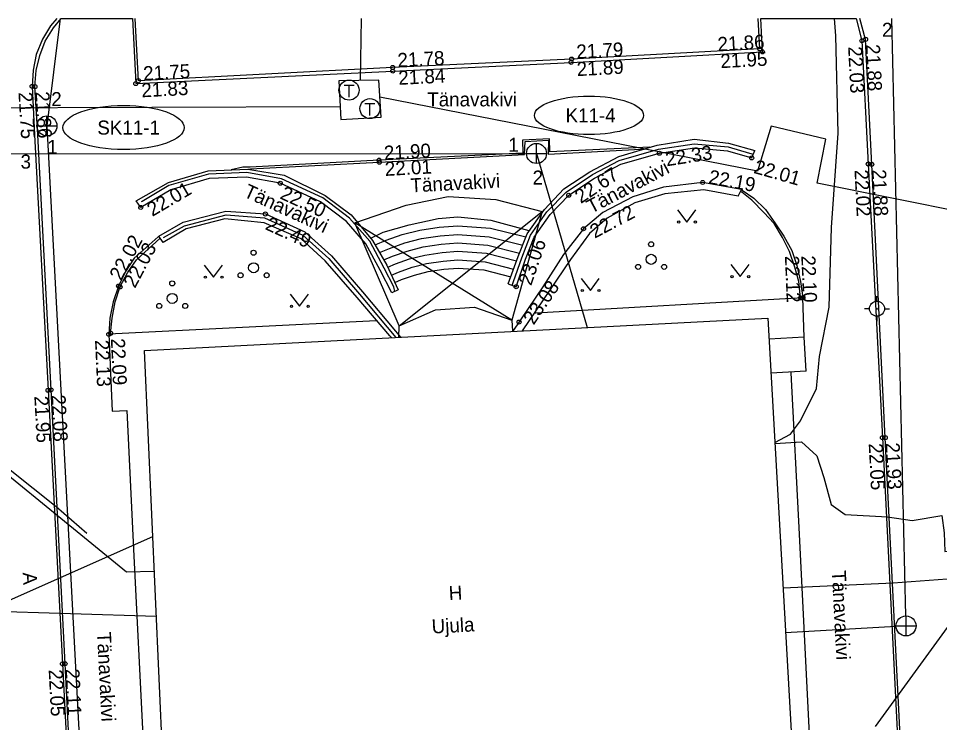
# Model space of a CAD drawing. Extents: x 714038 to 714279, y 6589845 to 6590041.
# Drawn here: x 714116.25 to 714162.18, y 6590005.87 to 6590040.97 of the extents above; entities that cross this region are included whole.
import ezdxf

# ---------------------------------------------------------------- set-up
doc = ezdxf.new("R2010")
doc.units = 0
for name, color, linetype in [('ALUSVORK', 7, 'Continuous'), ('HALJASTUS', 7, 'Continuous'), ('HOONE', 7, 'Continuous'), ('HOONEDET', 7, 'Continuous'), ('KAEVU_NR', 7, 'Continuous'), ('KKAEV', 7, 'Continuous'), ('KORGUS', 7, 'Continuous'), ('KTRASS', 7, 'Continuous'), ('LIIKLUS', 7, 'Continuous'), ('PUU', 7, 'Continuous'), ('RAJATIS', 7, 'Continuous'), ('SITRASS', 7, 'Continuous'), ('SKKAEV', 7, 'Continuous'), ('SKTRASS', 7, 'Continuous'), ('TEE', 7, 'Continuous'), ('TKAEV', 7, 'Continuous'), ('TORU NR', 7, 'Continuous'), ('TTRASS', 7, 'Continuous'), ('VTRASS', 7, 'Continuous')]:
    doc.layers.add(name, color=color, linetype=linetype)

msp = doc.modelspace()

# ---------------------------------------------------------------- linework, layer by layer
at = {"layer": 'ALUSVORK'}
for p, q in [((714159.055, 6590026.875), (714159.055, 6590027.125)), ((714158.68, 6590026.5), (714158.43, 6590026.5)), ((714159.43, 6590026.5), (714159.68, 6590026.5)), ((714159.055, 6590026.125), (714159.055, 6590025.875))]:
    msp.add_line(p, q, dxfattribs=at)
for radius in [0.375, 0.022]:
    msp.add_circle((714159.055, 6590026.5), radius, dxfattribs=at)
at = {"layer": 'HALJASTUS'}
for p, q in [((714149.109, 6590031.427), (714149.572, 6590030.82)), ((714149.572, 6590030.82), (714150.018, 6590031.427)), ((714151.77, 6590028.706), (714152.233, 6590028.099)), ((714152.233, 6590028.099), (714152.679, 6590028.706)), ((714125.51, 6590028.676), (714125.973, 6590028.069)), ((714125.973, 6590028.069), (714126.419, 6590028.676)), ((714144.3, 6590028.011), (714144.764, 6590027.404)), ((714144.764, 6590027.404), (714145.209, 6590028.011)), ((714129.804, 6590027.225), (714130.267, 6590026.618)), ((714130.267, 6590026.618), (714130.713, 6590027.225))]:
    msp.add_line(p, q, dxfattribs=at)
for centre in [(714149.171, 6590030.82), (714150, 6590030.82), (714125.572, 6590028.069), (714126.401, 6590028.069), (714151.832, 6590028.099), (714152.661, 6590028.099), (714144.363, 6590027.404), (714145.192, 6590027.404), (714129.866, 6590026.618), (714130.695, 6590026.618)]:
    msp.add_circle(centre, 0.055, dxfattribs=at)
at = {"layer": 'HOONE'}
for points in [[(714135.226, 6590025.643), (714133.02, 6590030.786), (714135.575, 6590031.653), (714137.67, 6590032.083), (714140.058, 6590031.943), (714142.37, 6590031.339), (714140.847, 6590025.921)], [(714123.806, 6589995.811), (714122.528, 6590024.418), (714153.616, 6590026.033), (714155.226, 6589997.511)]]:
    msp.add_lwpolyline(points, dxfattribs=at)
at = {"layer": 'HOONEDET'}
for p, q in [((714135.226, 6590025.643), (714137.049, 6590026.438)), ((714137.049, 6590026.438), (714138.994, 6590026.569)), ((714138.994, 6590026.569), (714140.847, 6590025.921)), ((714135.218, 6590025.061), (714135.226, 6590025.643)), ((714140.847, 6590025.921), (714140.89, 6590025.372))]:
    msp.add_line(p, q, dxfattribs=at)
for points in [[(714135.226, 6590025.643), (714142.37, 6590031.339)], [(714140.847, 6590025.921), (714133.02, 6590030.786)], [(714155.433, 6590025.074), (714155.354, 6590027.044), (714142.04, 6590026.282), (714141.962, 6590026.278)], [(714134.084, 6590025.899), (714120.754, 6590025.223), (714120.927, 6590021.387), (714121.652, 6590021.434), (714122.002, 6590014.168), (714122.456, 6590005.222), (714121.784, 6590005.188), (714122.031, 6590000.695), (714122.737, 6590000.728), (714122.997, 6589994.9)], [(714156.127, 6589996.644), (714155.189, 6590015.256), (714154.783, 6590023.3), (714154.78, 6590023.348)]]:
    msp.add_lwpolyline(points, dxfattribs=at)
at = {"layer": 'KAEVU_NR'}
for centre, major_axis, ratio in [((714144.698, 6590036.134), (2.717, 0), 0.353371), ((714121.489, 6590035.525), (-3.02, 0), 0.364056)]:
    msp.add_ellipse(centre, major_axis=major_axis, ratio=ratio, dxfattribs=at)
at = {"layer": 'KKAEV'}
for p, q in [((714142.079, 6590033.735), (714142.079, 6590034.735)), ((714141.579, 6590034.235), (714142.579, 6590034.235))]:
    msp.add_line(p, q, dxfattribs=at)
msp.add_circle((714142.079, 6590034.235), 0.5, dxfattribs=at)
at = {"layer": 'KORGUS'}
for centre in [(714158.303, 6590039.85), (714158.488, 6590039.922), (714153.206, 6590039.447), (714153.346, 6590039.301), (714143.807, 6590038.773), (714143.828, 6590038.94), (714134.905, 6590038.523), (714134.914, 6590038.34), (714122.227, 6590037.861), (714116.932, 6590037.581), (714117.073, 6590037.566), (714122.099, 6590037.718), (714148.204, 6590034.245), (714134.233, 6590033.901), (714134.24, 6590033.799), (714152.809, 6590034.015), (714158.62, 6590033.709), (714158.792, 6590033.69), (714129.303, 6590032.752), (714150.364, 6590032.791), (714143.685, 6590032.152), (714122.346, 6590031.544), (714128.561, 6590031.219), (714144.423, 6590030.482), (714121.241, 6590027.63), (714121.317, 6590027.583), (714141.065, 6590027.594), (714155.249, 6590027.039), (714155.365, 6590027.052), (714141.21, 6590025.833), (714120.754, 6590025.223), (714120.845, 6590025.268), (714117.725, 6590022.434), (714117.88, 6590022.454), (714159.328, 6590020.072), (714159.469, 6590020.069), (714118.442, 6590008.801), (714118.575, 6590008.805)]:
    msp.add_circle(centre, 0.1, dxfattribs=at)
at = {"layer": 'KTRASS'}
for points in [[(714115.68, 6590034.214), (714142.079, 6590034.235)], [(714142.079, 6590034.235), (714144.604, 6590025.565)], [(714114.583, 6590011.444), (714122.942, 6590015.15)], [(714114.552, 6590011.45), (714123.119, 6590011.176)]]:
    msp.add_lwpolyline(points, dxfattribs=at)
at = {"layer": 'LIIKLUS'}
for points in [[(714140.867, 6590027.663), (714140.94, 6590027.851), (714141.346, 6590029.032), (714141.78, 6590030.163), (714142.598, 6590031.322), (714143.555, 6590032.308), (714144.876, 6590033.184), (714146.201, 6590033.886), (714148.161, 6590034.442), (714149.946, 6590034.721), (714151.641, 6590034.558), (714152.696, 6590034.257), (714152.89, 6590034.197)], [(714135.022, 6590027.359), (714134.964, 6590027.582), (714134.492, 6590028.522), (714133.762, 6590029.857), (714132.758, 6590031.019), (714131.427, 6590032.024), (714129.372, 6590032.97), (714127.639, 6590033.286), (714125.728, 6590033.208), (714123.751, 6590032.632), (714122.417, 6590031.849), (714122.364, 6590031.817)], [(714123.48, 6590030.045), (714124.529, 6590030.636), (714126.607, 6590031.172), (714128.513, 6590031.032), (714130.421, 6590030.162), (714131.725, 6590028.997), (714133.258, 6590027.225), (714135.059, 6590025.069)]]:
    msp.add_lwpolyline(points, dxfattribs=at)
at = {"layer": 'PUU'}
for centre, radius in [((714147.794, 6590029.709), 0.125), ((714127.975, 6590029.289), 0.125), ((714147.794, 6590028.959), 0.25), ((714127.975, 6590028.539), 0.25), ((714147.144, 6590028.584), 0.125), ((714148.444, 6590028.584), 0.125), ((714127.325, 6590028.164), 0.125), ((714128.625, 6590028.164), 0.125), ((714123.918, 6590027.761), 0.125), ((714123.918, 6590027.011), 0.25), ((714123.268, 6590026.636), 0.125), ((714124.568, 6590026.636), 0.125)]:
    msp.add_circle(centre, radius, dxfattribs=at)
at = {"layer": 'RAJATIS'}
for points in [[(714140.669, 6590027.731), (714141.163, 6590029.094), (714141.621, 6590030.238), (714142.473, 6590031.441), (714143.444, 6590032.47), (714144.745, 6590033.323), (714146.189, 6590034.077), (714148.089, 6590034.653), (714149.934, 6590034.949), (714151.645, 6590034.754), (714152.971, 6590034.38)], [(714122.127, 6590031.875), (714123.731, 6590032.789), (714125.701, 6590033.373), (714127.689, 6590033.456), (714129.49, 6590033.162), (714131.541, 6590032.143), (714132.832, 6590031.178), (714133.908, 6590029.902), (714134.616, 6590028.673), (714135.185, 6590027.434)], [(714152.129, 6590032.115), (714150.424, 6590032.417), (714148.48, 6590032.232), (714146.989, 6590031.775), (714145.606, 6590031.016), (714144.718, 6590030.241), (714143.779, 6590028.953), (714141.364, 6590025.397)], [(714134.761, 6590025.155), (714133.131, 6590027.059), (714131.539, 6590028.891), (714130.341, 6590029.989), (714128.494, 6590030.777), (714126.533, 6590030.983), (714124.613, 6590030.487), (714123.467, 6590029.802)]]:
    msp.add_lwpolyline(points, dxfattribs=at)
at = {"layer": 'SITRASS'}
for points in [[(714153.966, 6590019.835), (714154.738, 6590020.25), (714155.241, 6590020.905), (714156.044, 6590022.523), (714156.187, 6590024.113), (714156.669, 6590026.569), (714156.78, 6590030.55), (714157.113, 6590035.251), (714157.004, 6590040.103), (714156.942, 6590040.965)], [(714119.667, 6590015.291), (714118.134, 6590016.633), (714114.596, 6590019.438), (714107.457, 6590025.877), (714104.409, 6590029.065), (714100.251, 6590033.606)], [(714153.969, 6590019.777), (714155.294, 6590019.865), (714156.05, 6590019.166), (714156.398, 6590018.084), (714156.778, 6590016.734), (714157.468, 6590016.238), (714159.581, 6590016.127), (714160.804, 6590015.95), (714162.282, 6590016.195), (714162.403, 6590015.338), (714162.44, 6590014.401), (714164.294, 6590014.521), (714168.017, 6590014.987), (714169.99, 6590015.378), (714173.537, 6590015.781), (714175.12, 6590015.912)], [(714154.374, 6590012.596), (714159.865, 6590012.844), (714163.01, 6590013.069), (714166.345, 6590013.02), (714169.914, 6590013.444), (714174.135, 6590014.18), (714175.181, 6590014.334)]]:
    msp.add_lwpolyline(points, dxfattribs=at)
at = {"layer": 'SKKAEV'}
for p, q in [((714117.671, 6590035.109), (714117.671, 6590036.109)), ((714117.171, 6590035.609), (714118.171, 6590035.609)), ((714160.503, 6590010.19), (714160.503, 6590011.19)), ((714160.003, 6590010.69), (714161.003, 6590010.69))]:
    msp.add_line(p, q, dxfattribs=at)
for centre in [(714117.671, 6590035.609), (714160.503, 6590010.69)]:
    msp.add_circle(centre, 0.5, dxfattribs=at)
at = {"layer": 'SKTRASS'}
for points in [[(714118.331, 6590040.965), (714117.671, 6590035.609)], [(714160.491, 6590011.19), (714159.788, 6590040.965)], [(714117.671, 6590035.609), (714120.007, 6589991.394)], [(714158.983, 6590005.685), (714168.6, 6590018.903)], [(714160.004, 6590010.662), (714154.501, 6590010.351)]]:
    msp.add_lwpolyline(points, dxfattribs=at)
at = {"layer": 'TEE'}
for p, q in [((714117.994, 6590040.489), (714118.385, 6590040.965)), ((714118.385, 6590040.965), (714121.944, 6590040.965)), ((714121.944, 6590040.965), (714122.099, 6590037.718)), ((714153.346, 6590039.301), (714153.258, 6590040.965)), ((714153.258, 6590040.965), (714158.012, 6590040.965)), ((714158.012, 6590040.965), (714158.303, 6590039.85)), ((714117.588, 6590039.837), (714117.994, 6590040.489)), ((714117.312, 6590039.111), (714117.588, 6590039.837)), ((714158.303, 6590039.85), (714158.62, 6590033.709)), ((714143.807, 6590038.773), (714153.346, 6590039.301)), ((714117.125, 6590038.378), (714117.312, 6590039.111)), ((714117.073, 6590037.566), (714117.125, 6590038.378)), ((714134.914, 6590038.34), (714143.807, 6590038.773)), ((714122.099, 6590037.718), (714134.914, 6590038.34)), ((714117.215, 6590035.159), (714117.073, 6590037.566)), ((714117.88, 6590022.454), (714117.215, 6590035.159)), ((714158.62, 6590033.709), (714159.328, 6590020.072)), ((714118.575, 6590008.805), (714117.88, 6590022.454)), ((714159.328, 6590020.072), (714160.175, 6590003.23)), ((714119.214, 6589995.92), (714118.575, 6590008.805))]:
    msp.add_line(p, q, dxfattribs=at)
for points in [[(714118.17, 6590040.965), (714117.844, 6590040.591), (714117.445, 6590039.93), (714117.134, 6590039.169), (714116.988, 6590038.386), (714116.932, 6590037.581), (714117.045, 6590035.166), (714117.725, 6590022.434), (714118.442, 6590008.801), (714119.224, 6589993.603), (714119.563, 6589992.698), (714120.198, 6589991.881), (714121.032, 6589991.362), (714122.012, 6589991.089), (714123.012, 6589991.123), (714130.695, 6589991.494), (714142.938, 6589992.169), (714155.474, 6589992.859)], [(714153.118, 6590040.965), (714153.206, 6590039.447), (714143.828, 6590038.94), (714134.905, 6590038.523), (714122.227, 6590037.861), (714122.077, 6590040.965)], [(714155.474, 6589992.859), (714155.637, 6589989.831), (714155.711, 6589989.359), (714155.917, 6589988.897), (714156.482, 6589988.156), (714156.88, 6589987.871), (714157.331, 6589987.632), (714157.808, 6589987.528), (714158.276, 6589987.496), (714158.764, 6589987.53), (714159.668, 6589987.878), (714160.04, 6589988.133), (714160.305, 6589988.353), (714160.603, 6589988.76), (714160.81, 6589989.189), (714160.975, 6589990.123), (714160.841, 6589993.165), (714160.313, 6590003.239), (714159.469, 6590020.069), (714158.792, 6590033.69), (714158.488, 6590039.922), (714158.196, 6590040.965)], [(714147.733, 6590034.545), (714142.751, 6590034.311), (714142.73, 6590034.965), (714141.382, 6590034.895), (714141.401, 6590034.256), (714134.233, 6590033.901), (714127.804, 6590033.559), (714127.445, 6590033.555), (714126.86, 6590033.421)], [(714127.689, 6590033.456), (714127.825, 6590033.468), (714134.24, 6590033.799), (714141.476, 6590034.185), (714141.507, 6590034.824), (714142.675, 6590034.896), (714142.657, 6590034.202), (714147.28, 6590034.455), (714147.451, 6590034.457)], [(714140.669, 6590027.731), (714141.065, 6590027.594), (714141.536, 6590028.963), (714141.959, 6590030.067), (714142.754, 6590031.193), (714143.685, 6590032.152), (714144.979, 6590033.01), (714146.277, 6590033.698), (714148.204, 6590034.245), (714149.952, 6590034.518), (714151.603, 6590034.359), (714152.809, 6590034.015), (714152.971, 6590034.38)], [(714135.185, 6590027.434), (714134.86, 6590027.283), (714134.291, 6590028.416), (714133.574, 6590029.727), (714132.602, 6590030.852), (714131.31, 6590031.828), (714129.303, 6590032.752), (714127.623, 6590033.058), (714125.765, 6590032.982), (714123.842, 6590032.422), (714122.346, 6590031.544), (714122.127, 6590031.875)], [(714152.129, 6590032.115), (714152.299, 6590032.432), (714150.364, 6590032.791), (714148.414, 6590032.563), (714146.88, 6590032.077), (714145.387, 6590031.29), (714144.423, 6590030.482), (714143.432, 6590029.201), (714142.399, 6590027.581), (714140.897, 6590025.372)], [(714152.299, 6590032.432), (714152.332, 6590032.402), (714152.914, 6590032.003), (714153.492, 6590031.438), (714153.965, 6590030.779), (714154.405, 6590030.106), (714154.813, 6590029.399), (714155.067, 6590028.656), (714155.25, 6590027.861), (714155.354, 6590027.044)], [(714155.354, 6590027.044), (714155.249, 6590027.039), (714155.158, 6590027.849), (714154.959, 6590028.564), (714154.689, 6590029.348), (714154.345, 6590030.048), (714153.93, 6590030.745), (714153.412, 6590031.3), (714152.815, 6590031.91), (714152.314, 6590032.304), (714152.248, 6590032.337)], [(714123.467, 6590029.802), (714123.255, 6590030.109), (714124.456, 6590030.814), (714126.59, 6590031.364), (714128.561, 6590031.219), (714130.526, 6590030.323), (714131.861, 6590029.131), (714133.403, 6590027.348), (714135.047, 6590025.381), (714135.297, 6590025.082)], [(714133.811, 6590030.017), (714134.43, 6590030.316), (714135.732, 6590030.685), (714135.732, 6590030.685), (714137.174, 6590030.995), (714138.16, 6590031.073), (714139.807, 6590030.91), (714141.7, 6590030.395)], [(714134.037, 6590029.679), (714134.587, 6590029.91), (714135.384, 6590030.193), (714136.263, 6590030.415), (714137.224, 6590030.563), (714138.161, 6590030.637), (714139.785, 6590030.517), (714141.555, 6590030.073)], [(714123.255, 6590030.109), (714123.212, 6590030.088), (714122.024, 6590029.016), (714121.579, 6590028.352), (714121.241, 6590027.63), (714120.975, 6590026.841), (714120.813, 6590026.034), (714120.754, 6590025.223)], [(714134.255, 6590029.3), (714134.744, 6590029.506), (714135.51, 6590029.778), (714136.349, 6590029.99), (714137.274, 6590030.132), (714138.162, 6590030.202), (714139.716, 6590030.087), (714141.392, 6590029.667)], [(714120.845, 6590025.268), (714120.922, 6590026.035), (714121.068, 6590026.846), (714121.326, 6590027.614), (714121.681, 6590028.281), (714122.133, 6590028.931), (714123.32, 6590030.016)], [(714134.467, 6590028.932), (714134.896, 6590029.113), (714135.632, 6590029.374), (714136.433, 6590029.576), (714137.323, 6590029.713), (714138.163, 6590029.779), (714139.648, 6590029.669), (714141.234, 6590029.272)], [(714134.663, 6590028.57), (714135.044, 6590028.731), (714135.751, 6590028.982), (714136.514, 6590029.174), (714137.37, 6590029.306), (714138.164, 6590029.368), (714139.583, 6590029.263), (714141.088, 6590028.887)], [(714134.845, 6590028.174), (714135.202, 6590028.324), (714135.878, 6590028.564), (714136.601, 6590028.746), (714137.42, 6590028.872), (714138.165, 6590028.931), (714139.513, 6590028.831), (714140.938, 6590028.474)], [(714135.014, 6590027.807), (714135.348, 6590027.947), (714135.995, 6590028.177), (714136.681, 6590028.35), (714137.467, 6590028.471), (714138.166, 6590028.526), (714139.449, 6590028.431), (714140.803, 6590028.092)], [(714134.761, 6590025.155), (714134.844, 6590025.058)], [(714155.52, 6590023.39), (714155.433, 6590025.074), (714153.676, 6590024.975)], [(714155.52, 6590023.39), (714153.771, 6590023.291)]]:
    msp.add_lwpolyline(points, dxfattribs=at)
at = {"layer": 'TKAEV'}
for p, q in [((714132.482, 6590037.642), (714132.982, 6590037.642)), ((714132.732, 6590037.042), (714132.732, 6590037.642)), ((714133.525, 6590036.721), (714134.025, 6590036.721)), ((714133.775, 6590036.121), (714133.775, 6590036.721))]:
    msp.add_line(p, q, dxfattribs=at)
for centre in [(714132.732, 6590037.392), (714133.775, 6590036.471)]:
    msp.add_circle(centre, 0.5, dxfattribs=at)
at = {"layer": 'TTRASS'}
for points in [[(714133.31, 6590037.87), (714133.351, 6590040.965)], [(714132.293, 6590036.559), (714113.5, 6590036.5), (714113.45, 6590038.15), (714110.55, 6590038.15), (714110.573, 6590036.38), (714092.848, 6590036.126)], [(714171.653, 6590030.531), (714167.33, 6590030.49), (714156.069, 6590032.753), (714156.51, 6590034.95), (714153.78, 6590035.59), (714153.09, 6590033.35), (714134.271, 6590037.038)]]:
    msp.add_lwpolyline(points, dxfattribs=at)
msp.add_lwpolyline([(714132.328, 6590035.93), (714134.328, 6590036.044), (714134.222, 6590037.893), (714132.223, 6590037.858)], close=True, dxfattribs=at)
at = {"layer": 'VTRASS'}
msp.add_lwpolyline([(714110.18, 6590040.965), (714110.16, 6590022.75), (714121.63, 6590013.38), (714123.019, 6590013.414)], dxfattribs=at)

# ---------------------------------------------------------------- texts
at = {"layer": 'HOONE'}
for s, p in [('H', (714137.721, 6590011.971)), ('Ujula', (714136.87, 6590010.309))]:
    msp.add_text(s, height=0.7, rotation=2.9733, dxfattribs=at).set_placement(p)
at = {"layer": 'KAEVU_NR'}
for s, p in [('K11-4', (714143.528, 6590035.784)), ('SK11-1', (714120.182, 6590035.175))]:
    msp.add_text(s, height=0.7, dxfattribs=at).set_placement(p)
at = {"layer": 'KORGUS'}
for s, rotation, p in [(' 21.79', 3.0946, (714143.828, 6590038.94)), (' 21.86', 3.1682, (714150.865, 6590039.317)), (' 21.78', 2.7875, (714134.905, 6590038.523)), (' 21.95', 3.1682, (714151.008, 6590038.471)), (' 22.03', 272.7927, (714157.604, 6590039.816)), (' 21.88', 272.7927, (714158.488, 6590039.922)), (' 21.89', 3.0946, (714143.845, 6590038.074)), (' 21.75', 2.9891, (714122.227, 6590037.861)), (' 21.84', 2.7875, (714134.948, 6590037.641)), (' 21.83', 2.9891, (714122.136, 6590037.019)), (' 21.75', 273.3762, (714116.233, 6590037.54)), (' 21.86', 273.3762, (714117.073, 6590037.566)), (' 21.90', 3.0535, (714134.233, 6590033.901)), (' 22.33', 8.8767, (714148.312, 6590033.553)), (' 22.01', 3.0535, (714134.277, 6590033.1)), (' 22.01', 344.0797, (714152.617, 6590033.342)), (' 22.67', 33.5468, (714144.072, 6590031.569)), (' 22.19', 349.4894, (714150.364, 6590032.791)), (' 22.02', 272.8454, (714157.921, 6590033.674)), (' 21.88', 272.8454, (714158.792, 6590033.69)), (' 22.01', 30.4086, (714122.7, 6590030.94)), (' 22.50', 335.2792, (714129.01, 6590032.116)), (' 22.72', 27.7949, (714144.749, 6590029.863)), (' 22.49', 335.488, (714128.271, 6590030.582)), (' 22.02', 61.9766, (714121.241, 6590027.63)), (' 22.03', 61.9766, (714121.935, 6590027.254)), (' 23.06', 71.0144, (714141.727, 6590027.366)), (' 22.12', 272.2964, (714154.454, 6590029.389)), (' 22.10', 272.2964, (714155.271, 6590029.395)), (' 23.08', 55.7762, (714141.789, 6590025.439)), (' 22.13', 272.5822, (714120.055, 6590025.191)), (' 22.09', 272.5822, (714120.845, 6590025.268)), (' 21.95', 273.0106, (714117.026, 6590022.397)), (' 22.08', 273.0106, (714117.88, 6590022.454)), (' 22.05', 272.8709, (714158.629, 6590020.037)), (' 21.93', 272.8709, (714159.469, 6590020.069)), (' 22.11', 272.8391, (714118.575, 6590008.805)), (' 22.05', 272.8391, (714117.743, 6590008.766))]:
    msp.add_text(s, height=0.7, rotation=rotation, dxfattribs=at).set_placement(p)
at = {"layer": 'TEE'}
msp.add_text('Tänavakivi', height=0.7, dxfattribs=at).set_placement((714136.633, 6590036.581))
for s, rotation, p in [('Tänavakivi', 27.7949, (714144.814, 6590031.217)), ('Tänavakivi', 3.0535, (714135.814, 6590032.292)), ('Tänavakivi', 335.488, (714127.426, 6590032.105)), ('A', 272.8364, (714116.463, 6590013.348)), ('Tänavakivi', 272.8851, (714156.803, 6590013.44)), ('Tänavakivi', 273.0106, (714120.161, 6590010.372))]:
    msp.add_text(s, height=0.7, rotation=rotation, dxfattribs=at).set_placement(p)
at = {"layer": 'TORU NR'}
for s, p in [('2', (714159.306, 6590040.05)), ('2', (714117.885, 6590036.593)), ('1', (714117.686, 6590034.213)), ('1', (714140.675, 6590034.318)), ('3', (714116.355, 6590033.48)), ('2', (714141.885, 6590032.685))]:
    msp.add_text(s, height=0.7, dxfattribs=at).set_placement(p)

doc.saveas('drawing.dxf')
